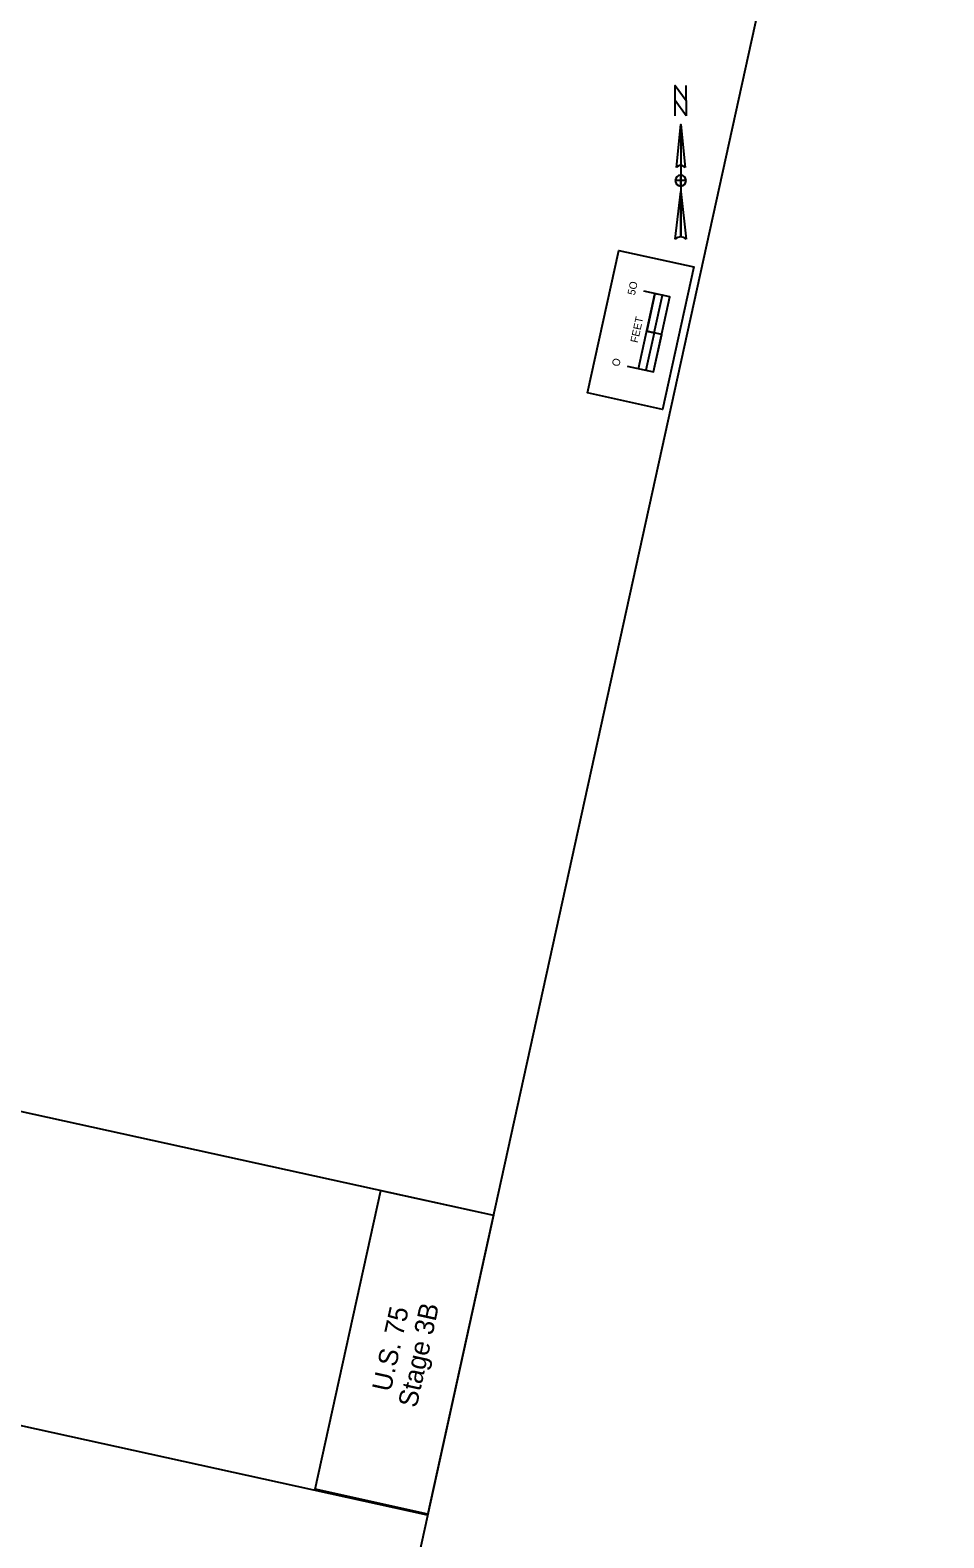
# Model space of a CAD drawing. Extents: x 14104283 to 14128447, y 8633203 to 8671666.
# Drawn here: x 14107946 to 14108541, y 8638411 to 8639393 of the extents above; entities that cross this region are included whole.
import ezdxf

# ---------------------------------------------------------------- set-up
doc = ezdxf.new("R2010")
doc.units = 0
for name, color, linetype in [('dsnCellsNorthArrow', 7, 'Continuous'), ('dsnCellsScaleBlock', 7, 'Continuous'), ('dsnNonPlotable', 7, 'Continuous'), ('dsnTextOverlapOdd', 7, 'Continuous')]:
    doc.layers.add(name, color=color, linetype=linetype)

msp = doc.modelspace()

# ---------------------------------------------------------------- linework, layer by layer
at = {"layer": 'dsnCellsNorthArrow'}
for p, q in [((14108369.85, 8639331.32), (14108372.67, 8639303.15)), ((14108369.85, 8639331.32), (14108369.85, 8639258.08)), ((14108367.03, 8639303.15), (14108367.03, 8639303.15)), ((14108367.14, 8639303.42), (14108367.67, 8639304)), ((14108366.33, 8639256.67), (14108369.85, 8639287.66)), ((14108369.85, 8639291.18), (14108369.85, 8639291.18))]:
    msp.add_line(p, q, dxfattribs=at)
msp.add_lwpolyline([(14108373.37, 8639336.96), (14108366.33, 8639346.82), (14108366.33, 8639356.68), (14108373.37, 8639346.82)], close=True, dxfattribs=at)
for points in [[(14108366.33, 8639336.96), (14108366.33, 8639356.68), (14108373.37, 8639346.82), (14108373.37, 8639356.68)], [(14108367.03, 8639303.15), (14108369.85, 8639331.32), (14108369.85, 8639304.56)], [(14108369.85, 8639291.18), (14108369.85, 8639294.7), (14108366.33, 8639294.7)], [(14108373.37, 8639294.7), (14108369.85, 8639294.7), (14108369.85, 8639298.22)], [(14108369.85, 8639258.08), (14108369.85, 8639287.66), (14108373.37, 8639256.67)]]:
    msp.add_lwpolyline(points, dxfattribs=at)
for centre, radius, start, end in [((14108369.85, 8639301.04), 3.52, 90.02039, 143.12574), ((14108369.85, 8639301.04), 3.52, 36.84806, 90.02184), ((14108369.85, 8639294.7), 3.52, 90, 180), ((14108369.85, 8639294.7), 3.52, 180, 270), ((14108369.85, 8639294.7), 3.52, 0, 90), ((14108369.85, 8639294.7), 3.52, 270, 360), ((14108369.85, 8639252.98), 5.1, 89.98939, 133.61895), ((14108369.85, 8639252.97), 5.11, 46.40206, 90.00064)]:
    msp.add_arc(centre, radius, start, end, dxfattribs=at)
at = {"layer": 'dsnCellsScaleBlock'}
msp.add_line((14108357.48, 8639194.5), (14108347.71, 8639196.65), dxfattribs=at)
msp.add_line((14108357.48, 8639194.5), (14108347.71, 8639196.65), dxfattribs=at)
for points in [[(14108358.03, 8639145.75), (14108309.19, 8639156.48), (14108329.58, 8639249.26), (14108378.42, 8639238.53)], [(14108309.19, 8639156.48), (14108329.58, 8639249.26), (14108378.42, 8639238.53), (14108358.03, 8639145.75)], [(14108358.03, 8639145.75), (14108309.19, 8639156.48), (14108329.58, 8639249.26), (14108378.42, 8639238.53)], [(14108352.56, 8639195.58), (14108357.93, 8639220), (14108353.08, 8639221.07), (14108347.71, 8639196.65)], [(14108352.11, 8639170.08), (14108357.48, 8639194.5), (14108352.56, 8639195.58), (14108347.2, 8639171.17)]]:
    msp.add_lwpolyline(points, close=True, dxfattribs=at)
for points in [[(14108335.02, 8639173.84), (14108352.11, 8639170.08), (14108362.84, 8639218.92), (14108345.75, 8639222.68)], [(14108342.35, 8639172.23), (14108353.08, 8639221.07)]]:
    msp.add_lwpolyline(points, dxfattribs=at)
at = {"layer": 'dsnNonPlotable'}
for points in [[(14107218.44, 8638642.33), (14107554.83, 8640173.31), (14108541.3, 8639956.56), (14108204.91, 8638425.58)], [(14106924.98, 8637306.69), (14107261.36, 8638837.67), (14108247.83, 8638620.92), (14107911.44, 8637089.94)]]:
    msp.add_lwpolyline(points, close=True, dxfattribs=at)
at = {"layer": 'dsnTextOverlapOdd'}
for points in [[(14108247.83, 8638620.92), (14108205.07, 8638426.28), (14108131.81, 8638442.38), (14108174.58, 8638637.01)], [(14108131.81, 8638442.38), (14108174.58, 8638637.01), (14108247.83, 8638620.92), (14108205.07, 8638426.28)]]:
    msp.add_lwpolyline(points, close=True, dxfattribs=at)

# ---------------------------------------------------------------- texts
at = {"layer": 'dsnCellsScaleBlock'}
for s, p in [('5O', (14108339.99, 8639219.77)), ('FEET', (14108341.88, 8639188.74)), ('O', (14108329.79, 8639173.32))]:
    msp.add_text(s, height=5, rotation=77.60784, dxfattribs=at).set_placement(p)
at = {"layer": 'dsnTextOverlapOdd'}
for s, p in [('U.S. 75', (14108180.85, 8638505.36)), ('Stage 3B', (14108197.77, 8638494.99))]:
    msp.add_text(s, height=12.5, rotation=77.60784, dxfattribs=at).set_placement(p)

doc.saveas('drawing.dxf')
